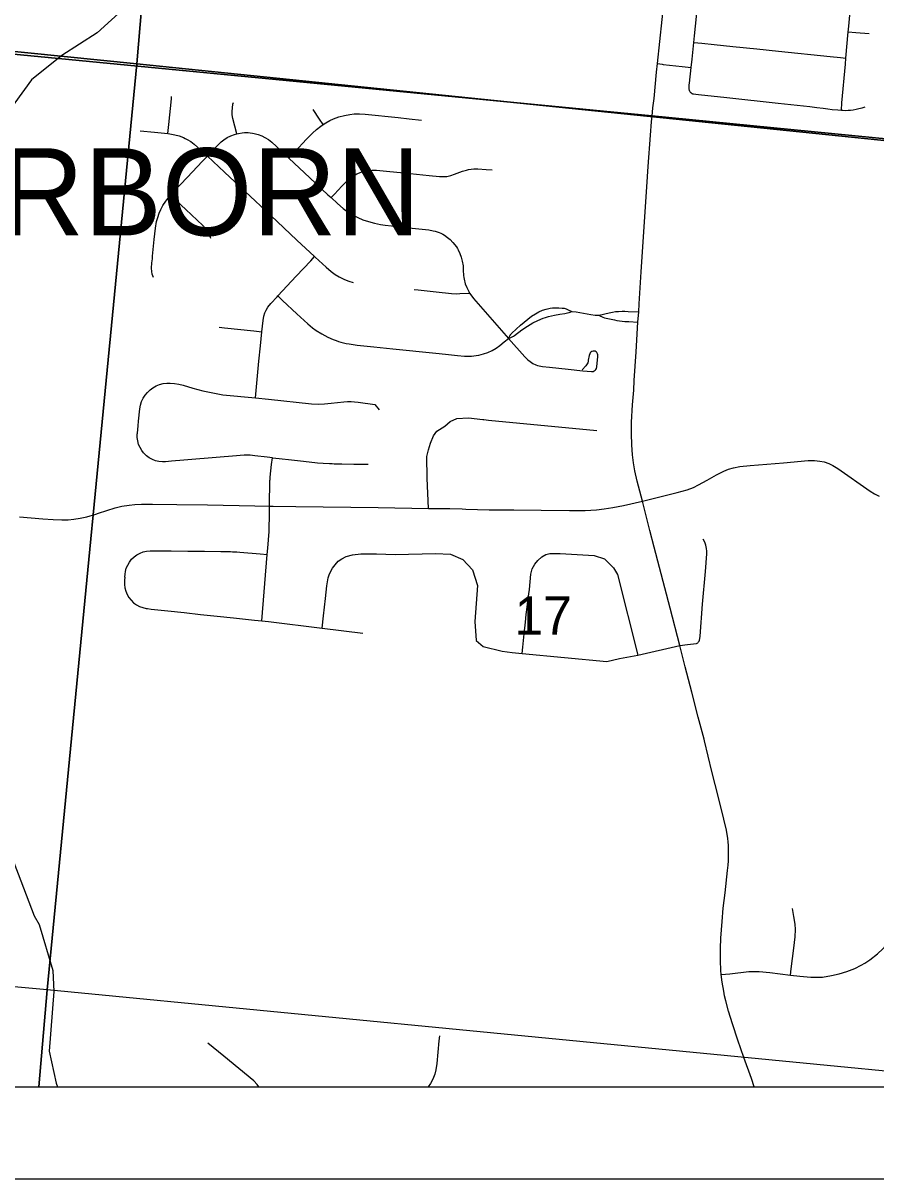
# Model space of a CAD drawing. Extents: x 0 to 34, y 0 to 22.
# Drawn here: x 26.733 to 27.66, y 13.362 to 14.618 of the extents above; entities that cross this region are included whole.
import ezdxf

# ---------------------------------------------------------------- set-up
doc = ezdxf.new("R2010")
doc.units = 0
for name, color, linetype in [('GM_X_City_Street', 7, 'Continuous'), ('GM_X_Corporation_Text', 7, 'Continuous'), ('GM_X_County_Road', 7, 'Continuous'), ('GM_X_Minor_River', 7, 'Continuous'), ('GM_X_Section', 7, 'Continuous'), ('GM_X_Section_Text', 7, 'Continuous'), ('GM_X_Township_Road', 7, 'Continuous'), ('SH_Border', 7, 'Continuous'), ('SH_Data', 7, 'Continuous')]:
    doc.layers.add(name, color=color, linetype=linetype)

msp = doc.modelspace()

# ---------------------------------------------------------------- linework, layer by layer
at = {"layer": 'GM_X_City_Street'}
for points in [[(27.6225, 14.5232), (27.6232, 14.5311), (27.6269, 14.5732), (27.6275, 14.5797), (27.63, 14.6083), (27.6303, 14.611), (27.632, 14.63), (27.6354, 14.6657), (27.6359, 14.6704), (27.6403, 14.7174), (27.6409, 14.7237), (27.6441, 14.7601), (27.6449, 14.77), (27.6454, 14.7759)], [(27.4592, 14.5419), (27.4586, 14.5424), (27.4581, 14.5431), (27.4578, 14.5437), (27.4575, 14.5443), (27.4573, 14.545), (27.4571, 14.5456), (27.457, 14.5463), (27.457, 14.5477), (27.4571, 14.5506), (27.4573, 14.5527), (27.4592, 14.5697), (27.4603, 14.5787), (27.4622, 14.5969), (27.463, 14.604), (27.4665, 14.6393)], [(27.63, 14.6083), (27.6381, 14.6076), (27.6528, 14.6065)], [(27.4622, 14.5969), (27.4707, 14.5961), (27.4843, 14.5947), (27.5047, 14.5925), (27.5307, 14.5898), (27.5542, 14.5873), (27.6105, 14.5814), (27.6217, 14.5803), (27.6275, 14.5797)], [(27.4226, 14.5738), (27.4278, 14.5731), (27.429, 14.573), (27.4495, 14.5707), (27.4592, 14.5697)], [(26.8905, 14.4977), (26.8914, 14.5075), (26.8943, 14.5354), (26.8946, 14.5379)], [(27.4592, 14.5419), (27.4603, 14.5413), (27.4609, 14.5411), (27.4617, 14.5409), (27.4642, 14.5405), (27.4673, 14.5402), (27.4982, 14.537), (27.5539, 14.531), (27.5883, 14.5272), (27.596, 14.5262), (27.6028, 14.5253), (27.6079, 14.5247), (27.6127, 14.5241), (27.6187, 14.5235), (27.6225, 14.5232), (27.6242, 14.5231), (27.6274, 14.523), (27.6299, 14.5231), (27.6324, 14.5232), (27.6352, 14.5235), (27.6385, 14.5242), (27.6414, 14.5249), (27.645, 14.5257), (27.6485, 14.5267)], [(26.9653, 14.4975), (26.9632, 14.5058), (26.9611, 14.5143), (26.9605, 14.5181), (26.9603, 14.52), (26.9603, 14.5219), (26.9606, 14.5258), (26.9612, 14.5296), (26.9617, 14.5314)], [(27.0592, 14.5076), (27.0553, 14.5134), (27.0483, 14.5241)], [(27.0219, 14.4712), (27.0284, 14.478), (27.0412, 14.4916), (27.0477, 14.4984), (27.0519, 14.5022), (27.0568, 14.506), (27.0592, 14.5076), (27.0621, 14.5095), (27.0665, 14.512), (27.0705, 14.5138), (27.0764, 14.5159), (27.0825, 14.5176), (27.0881, 14.5186), (27.0931, 14.5192), (27.0988, 14.5194), (27.105, 14.519), (27.1409, 14.5152), (27.1527, 14.5139), (27.1662, 14.5123)], [(26.8604, 14.5009), (26.8759, 14.4993), (26.8905, 14.4977), (26.8925, 14.4975), (26.898, 14.4966), (26.9027, 14.4953), (26.9073, 14.4936), (26.9093, 14.4926), (26.9116, 14.4915), (26.9153, 14.4892), (26.9192, 14.4863), (26.9261, 14.4802), (26.9334, 14.4734), (26.9519, 14.456), (26.9746, 14.4348), (27.0023, 14.4089), (27.0308, 14.3821), (27.05, 14.3641), (27.0507, 14.3634), (27.0626, 14.3525), (27.0679, 14.348), (27.0725, 14.3447), (27.0768, 14.3421), (27.0825, 14.3393), (27.0871, 14.3375), (27.092, 14.336)], [(26.8747, 14.3414), (26.8735, 14.345), (26.8729, 14.348), (26.8727, 14.3517), (26.8731, 14.3573), (26.8736, 14.3616), (26.8738, 14.3647), (26.8757, 14.3826), (26.8771, 14.395), (26.8783, 14.4023), (26.8794, 14.4066), (26.881, 14.4113), (26.8827, 14.4152), (26.8851, 14.4196), (26.8882, 14.4243), (26.8916, 14.4287), (26.8932, 14.4305), (26.8969, 14.4348), (26.9115, 14.4501), (26.9281, 14.4678), (26.9334, 14.4734), (26.9443, 14.4849), (26.9483, 14.4888), (26.9513, 14.4911), (26.955, 14.4934), (26.9589, 14.4953), (26.9629, 14.4969), (26.9653, 14.4975), (26.9671, 14.498), (26.9714, 14.4987), (26.9737, 14.4989), (26.9759, 14.4989), (26.9779, 14.4988), (26.9801, 14.4986), (26.9823, 14.4983), (26.9844, 14.4979), (26.9886, 14.4968), (26.9926, 14.4952), (26.996, 14.4936), (26.9997, 14.4913), (27.0036, 14.4883), (27.0087, 14.4836), (27.0219, 14.4712), (27.0449, 14.4497), (27.0644, 14.4313), (27.0678, 14.4282), (27.0749, 14.4217), (27.0811, 14.4165), (27.0866, 14.4124), (27.0918, 14.4091), (27.0968, 14.4065), (27.1025, 14.4041), (27.1084, 14.4021), (27.115, 14.4003), (27.1217, 14.399), (27.1268, 14.3983), (27.1337, 14.3974), (27.1455, 14.3962), (27.1595, 14.3948), (27.1741, 14.3931), (27.179, 14.3921), (27.1811, 14.3916), (27.1831, 14.3909), (27.1852, 14.3902), (27.1872, 14.3894), (27.1892, 14.3884), (27.191, 14.3874), (27.1946, 14.385), (27.1974, 14.3826), (27.2004, 14.3794), (27.2043, 14.3746), (27.2054, 14.3729), (27.2062, 14.3714), (27.208, 14.3674), (27.2094, 14.3633), (27.2105, 14.3591), (27.2113, 14.3542), (27.2115, 14.3493), (27.2118, 14.3437), (27.2121, 14.3413), (27.2125, 14.3394), (27.2138, 14.3346), (27.2153, 14.3305), (27.2175, 14.326), (27.2185, 14.3244), (27.2198, 14.3224), (27.2228, 14.3184), (27.2428, 14.2955), (27.2608, 14.2752), (27.2786, 14.255), (27.2816, 14.2519), (27.2841, 14.25), (27.2873, 14.248), (27.2906, 14.2465), (27.2924, 14.2458), (27.2942, 14.2453), (27.2978, 14.2446), (27.3053, 14.2438), (27.3256, 14.2416), (27.3417, 14.2401), (27.351, 14.2393), (27.3529, 14.2394), (27.354, 14.2398), (27.355, 14.2405), (27.3558, 14.2414), (27.3564, 14.2425), (27.3568, 14.2444), (27.3579, 14.2555), (27.3578, 14.2574), (27.3575, 14.2586), (27.3569, 14.2597), (27.356, 14.2605), (27.355, 14.2612), (27.3538, 14.2615), (27.3526, 14.2615), (27.3514, 14.2611), (27.3504, 14.2603), (27.3496, 14.2594), (27.349, 14.2583), (27.3484, 14.2566), (27.3475, 14.2516), (27.3472, 14.2498), (27.3468, 14.2487), (27.3463, 14.2475), (27.3456, 14.2464), (27.3449, 14.2454), (27.3408, 14.2411)], [(27.0678, 14.4282), (27.0715, 14.4321), (27.0795, 14.4408), (27.0853, 14.4465), (27.0891, 14.4498), (27.0922, 14.4519), (27.096, 14.4539), (27.1006, 14.4559), (27.1041, 14.457), (27.1084, 14.4578), (27.1127, 14.4582), (27.1171, 14.4582), (27.1283, 14.4571), (27.1468, 14.4551), (27.1746, 14.4521), (27.1858, 14.4511), (27.1907, 14.451), (27.1938, 14.4513), (27.1981, 14.4522), (27.2022, 14.4535), (27.2109, 14.4569), (27.215, 14.4582), (27.2174, 14.4588), (27.223, 14.4594), (27.2273, 14.4594), (27.2366, 14.4588), (27.2428, 14.4583)], [(26.9372, 14.3838), (26.9368, 14.385), (26.9351, 14.389), (26.9333, 14.3922), (26.9314, 14.3947), (26.9285, 14.3978), (26.91, 14.4153), (26.8995, 14.4249), (26.8932, 14.4305)], [(26.9892, 14.2503), (26.991, 14.267), (26.9927, 14.2825), (26.994, 14.2948), (26.9949, 14.2992), (26.996, 14.3029), (26.9973, 14.3058), (26.9993, 14.3091), (27.0025, 14.3131), (27.0092, 14.3205), (27.0099, 14.3213), (27.03, 14.3428), (27.0457, 14.3595), (27.05, 14.3641)], [(27.0099, 14.3213), (27.0152, 14.3164), (27.0306, 14.302), (27.0425, 14.291), (27.0477, 14.2866), (27.0518, 14.2837), (27.0577, 14.28), (27.0644, 14.2765), (27.0701, 14.274), (27.0734, 14.2728), (27.076, 14.2719), (27.0786, 14.2712), (27.0815, 14.2704), (27.0844, 14.2697), (27.0876, 14.2692), (27.0963, 14.268), (27.1142, 14.2662), (27.1351, 14.264), (27.1817, 14.259), (27.1924, 14.2579), (27.2054, 14.2566), (27.2128, 14.2559), (27.2179, 14.2558), (27.2204, 14.2559), (27.2229, 14.2562), (27.2257, 14.2565), (27.2285, 14.2571), (27.2334, 14.2583), (27.2382, 14.2599), (27.2428, 14.262), (27.2472, 14.2645), (27.2513, 14.2674), (27.2561, 14.2714), (27.2608, 14.2752)], [(27.1582, 14.3285), (27.1624, 14.328), (27.182, 14.3257), (27.1986, 14.3241), (27.2047, 14.3237), (27.2078, 14.3239), (27.2185, 14.3244)], [(27.2608, 14.2752), (27.2622, 14.2779), (27.2631, 14.2795), (27.2637, 14.2803), (27.2644, 14.281), (27.2738, 14.2894), (27.2858, 14.2992), (27.2899, 14.302), (27.2937, 14.3041), (27.2977, 14.3058), (27.3018, 14.3071), (27.3061, 14.308), (27.3084, 14.3083), (27.311, 14.3085), (27.3153, 14.3085), (27.3191, 14.3082), (27.3213, 14.3079), (27.3233, 14.3074), (27.3257, 14.3064), (27.3294, 14.3046)], [(27.2608, 14.2752), (27.2633, 14.2761), (27.2648, 14.2768), (27.2662, 14.2775), (27.2673, 14.2782), (27.2751, 14.2844), (27.2813, 14.2886), (27.2871, 14.2921), (27.2927, 14.2948), (27.2984, 14.2971), (27.301, 14.298), (27.3043, 14.299), (27.3109, 14.3006), (27.3164, 14.3016), (27.3219, 14.3023), (27.3235, 14.3025), (27.3248, 14.3028), (27.3268, 14.3034), (27.3294, 14.3046)], [(27.3294, 14.3046), (27.3342, 14.3039), (27.3501, 14.3011), (27.3548, 14.3006), (27.3594, 14.3003)], [(27.3594, 14.3003), (27.3701, 14.303), (27.3738, 14.3038), (27.3772, 14.3044), (27.3802, 14.3046), (27.3841, 14.3048), (27.3872, 14.3048), (27.3908, 14.3046), (27.4023, 14.304)], [(27.3594, 14.3003), (27.361, 14.2993), (27.3632, 14.2983), (27.3652, 14.2977), (27.3686, 14.2968), (27.376, 14.2952), (27.3785, 14.2947), (27.3815, 14.2943), (27.3842, 14.294), (27.387, 14.2937), (27.3914, 14.2935), (27.4014, 14.2928)], [(26.9464, 14.2875), (26.952, 14.2867), (26.9841, 14.2834), (26.9927, 14.2825)]]:
    msp.add_lwpolyline(points, dxfattribs=at)
at = {"layer": 'GM_X_County_Road'}
for p, q in [((27.4226, 14.5738), (27.4312, 14.6557)), ((27.4014, 14.2928), (27.4023, 14.304))]:
    msp.add_line(p, q, dxfattribs=at)
for points in [[(27.4168, 14.5166), (27.4177, 14.5256), (27.4189, 14.536), (27.4216, 14.5644), (27.4226, 14.5738)], [(27.4023, 14.304), (27.4029, 14.3129), (27.4049, 14.3476), (27.411, 14.4398), (27.4125, 14.4621), (27.4151, 14.4962), (27.4162, 14.5104), (27.4168, 14.5166)], [(27.3956, 14.2031), (27.3968, 14.219), (27.3973, 14.2296), (27.3995, 14.2607), (27.4014, 14.2928)], [(27.4062, 14.0982), (27.4004, 14.1202), (27.398, 14.1311), (27.3965, 14.1398), (27.3954, 14.1485), (27.3947, 14.1597), (27.3944, 14.1716), (27.3946, 14.1841), (27.3956, 14.2031)], [(26.8152, 14.0851), (26.8333, 14.091), (26.8405, 14.0927), (26.8484, 14.0941), (26.8545, 14.0947), (26.8619, 14.0951), (26.8737, 14.0951), (26.9004, 14.0946), (26.9334, 14.0942), (26.9849, 14.0932), (27.001, 14.0929)], [(27.001, 14.0929), (27.0048, 14.0928), (27.0297, 14.0926), (27.1192, 14.0913), (27.1739, 14.0904), (27.1969, 14.0902), (27.2102, 14.0898)], [(27.2102, 14.0898), (27.2142, 14.0897), (27.2397, 14.0889), (27.2664, 14.0888), (27.2962, 14.0885), (27.3269, 14.088), (27.344, 14.0882), (27.3565, 14.089), (27.3647, 14.0899), (27.374, 14.0913), (27.3857, 14.0935), (27.4062, 14.0982)], [(27.4469, 13.9416), (27.4365, 13.9822), (27.4191, 14.0483), (27.4144, 14.0663), (27.4062, 14.0982)], [(26.7293, 14.0812), (26.7547, 14.0791), (26.7659, 14.0783), (26.7752, 14.078), (26.7821, 14.0781), (26.7884, 14.0787), (26.7952, 14.0798), (26.8025, 14.0814), (26.8121, 14.0841), (26.8152, 14.0851)], [(27.4737, 13.8379), (27.4733, 13.8398), (27.467, 13.8637), (27.46, 13.8907), (27.4529, 13.9184), (27.4469, 13.9416)], [(27.492, 13.5838), (27.4916, 13.5883), (27.4914, 13.5917), (27.4913, 13.596), (27.4911, 13.6007), (27.4911, 13.6071), (27.4912, 13.6123), (27.4916, 13.6235), (27.4929, 13.6415), (27.4942, 13.656), (27.4961, 13.6726), (27.4989, 13.6971), (27.4994, 13.7027), (27.4997, 13.7076), (27.4999, 13.7125), (27.4999, 13.7168), (27.5, 13.7207), (27.4998, 13.7242), (27.4995, 13.7281), (27.4991, 13.7316), (27.4975, 13.7407), (27.4949, 13.7528), (27.4891, 13.7763), (27.4819, 13.8046), (27.4737, 13.8379)], [(27.5276, 13.4618), (27.5247, 13.4709), (27.5166, 13.4937), (27.5099, 13.5125), (27.5041, 13.5302), (27.5, 13.5439), (27.4969, 13.5553), (27.4956, 13.5609), (27.4947, 13.5657), (27.493, 13.5756), (27.492, 13.5838)]]:
    msp.add_lwpolyline(points, dxfattribs=at)
for points in [[(25.742, 13.4618), (26.7501, 13.4618), (26.7594, 13.5671), (25.7609, 13.6582)], [(26.7501, 13.4618), (27.7745, 13.4618), (27.7751, 13.4688), (26.7594, 13.5671)]]:
    msp.add_lwpolyline(points, close=True, dxfattribs=at)
at = {"layer": 'GM_X_Minor_River'}
for points in [[(26.8565, 14.6464), (26.8136, 14.6074), (26.7752, 14.5827), (26.7424, 14.5561), (26.7026, 14.5022)], [(26.7087, 13.7437), (26.7451, 13.6477), (26.7506, 13.6381), (26.7655, 13.5881), (26.7666, 13.5656), (26.7615, 13.5005), (26.7691, 13.4658), (26.7707, 13.4618)]]:
    msp.add_lwpolyline(points, dxfattribs=at)
at = {"layer": 'GM_X_Section'}
for points in [[(26.9382, 15.5362), (26.8568, 14.5735), (25.8618, 14.6744), (25.9494, 15.6396)], [(26.9382, 15.5362), (27.9506, 15.429), (27.8702, 14.4696), (26.8568, 14.5735)], [(26.8568, 14.5735), (26.7594, 13.5671), (25.7609, 13.6582), (25.8618, 14.6744)], [(26.8568, 14.5735), (27.8702, 14.4696), (27.7751, 13.4688), (26.7594, 13.5671)]]:
    msp.add_lwpolyline(points, close=True, dxfattribs=at)
at = {"layer": 'GM_X_Township_Road'}
for p, q in [((26.9856, 14.2106), (26.9892, 14.2503)), ((26.9925, 13.9682), (26.9985, 14.0404)), ((27.0581, 13.9603), (27.1024, 13.9549))]:
    msp.add_line(p, q, dxfattribs=at)
for points in [[(26.8587, 14.1854), (26.86, 14.1988), (26.8608, 14.2027), (26.862, 14.2065), (26.8637, 14.2101), (26.8658, 14.2134), (26.8683, 14.2165), (26.8711, 14.2192), (26.8743, 14.2216), (26.8778, 14.2235), (26.8814, 14.225), (26.8852, 14.2261), (26.8892, 14.2267), (26.8931, 14.2267), (26.8978, 14.2262), (26.9025, 14.2254), (26.9071, 14.2243), (26.9177, 14.2211), (26.9284, 14.2183), (26.9392, 14.2159), (26.9501, 14.214), (26.9856, 14.2106)], [(26.9856, 14.2106), (26.9998, 14.209), (27.0467, 14.204), (27.0538, 14.2039), (27.0609, 14.2042), (27.068, 14.2048), (27.0819, 14.2062), (27.0857, 14.2066), (27.0896, 14.2066), (27.0935, 14.2064), (27.0974, 14.2059), (27.1155, 14.2032), (27.1203, 14.1977)], [(27.0041, 14.1455), (26.9983, 14.1461), (26.9851, 14.1476), (26.9799, 14.1482), (26.9758, 14.1483), (26.9744, 14.1482), (26.9734, 14.1482), (26.9607, 14.1471), (26.9475, 14.146), (26.9342, 14.1449), (26.921, 14.1438), (26.9078, 14.1427), (26.8946, 14.1416), (26.8879, 14.141), (26.8846, 14.1409), (26.8808, 14.1413), (26.8772, 14.1422), (26.8736, 14.1436), (26.8703, 14.1454), (26.8672, 14.1476), (26.8645, 14.1503), (26.8639, 14.151), (26.8621, 14.1532), (26.8602, 14.1565), (26.8587, 14.16), (26.8577, 14.1637), (26.8572, 14.1674), (26.8572, 14.1712), (26.8573, 14.1722), (26.8581, 14.18), (26.8587, 14.1854)], [(27.1739, 14.0904), (27.1725, 14.1232), (27.1718, 14.1468), (27.1738, 14.1541), (27.1758, 14.1613), (27.1791, 14.1692), (27.183, 14.1745), (27.1916, 14.1797), (27.1975, 14.185), (27.2047, 14.1883), (27.2172, 14.1889), (27.233, 14.187)], [(27.233, 14.187), (27.234, 14.1869), (27.2389, 14.1863), (27.3568, 14.175)], [(27.001, 14.0929), (27.0011, 14.105), (27.0012, 14.1097), (27.0014, 14.1192), (27.0014, 14.1207), (27.0015, 14.1219), (27.0018, 14.1245), (27.0033, 14.138), (27.0041, 14.1455)], [(27.0041, 14.1455), (27.0115, 14.1447), (27.0247, 14.1433), (27.0379, 14.1418), (27.0532, 14.1401), (27.0593, 14.1396), (27.0661, 14.1392), (27.069, 14.1391), (27.0711, 14.139), (27.0794, 14.1389), (27.0927, 14.1387), (27.1081, 14.1385)], [(27.4062, 14.0982), (27.4442, 14.1079), (27.455, 14.1108), (27.4619, 14.1132), (27.4674, 14.1159), (27.4765, 14.1211), (27.4867, 14.1271), (27.4946, 14.131), (27.4998, 14.1331), (27.5053, 14.1347), (27.5121, 14.1359), (27.5233, 14.137), (27.5598, 14.1401), (27.5865, 14.1424), (27.5934, 14.1425), (27.5991, 14.1419), (27.604, 14.1409), (27.6088, 14.1392), (27.6134, 14.137), (27.6188, 14.1337), (27.6539, 14.1092), (27.6587, 14.1063), (27.6636, 14.1039)], [(26.9985, 14.0404), (26.999, 14.0473), (27.0005, 14.0652), (27.0007, 14.0686), (27.0008, 14.0827), (27.001, 14.0929)], [(27.4469, 13.9416), (27.4554, 13.9426), (27.465, 13.9437), (27.4658, 13.9439), (27.4664, 13.9443), (27.467, 13.9449), (27.4674, 13.9454), (27.4679, 13.9463), (27.4683, 13.9474), (27.4686, 13.949), (27.4689, 13.9516), (27.4717, 13.9863), (27.4747, 14.0217), (27.4763, 14.0409), (27.4764, 14.0438), (27.4761, 14.0467), (27.4757, 14.0488), (27.4752, 14.0506), (27.4746, 14.0525), (27.4737, 14.0545), (27.4723, 14.057)], [(26.8436, 14.0156), (26.8439, 14.0188), (26.8443, 14.0217), (26.8453, 14.0254), (26.8468, 14.0289), (26.8487, 14.0322), (26.8511, 14.0351), (26.8538, 14.0378), (26.8569, 14.04), (26.8602, 14.0419), (26.8637, 14.0432), (26.8674, 14.0441), (26.8712, 14.0445), (26.8725, 14.0445), (26.8762, 14.0444), (26.8942, 14.0442), (26.9122, 14.044), (26.9302, 14.0438), (26.9482, 14.0436), (26.9586, 14.0435), (26.9609, 14.0434), (26.9653, 14.0431), (26.9687, 14.0429), (26.9909, 14.041), (26.9985, 14.0404)], [(27.0581, 13.9603), (27.0595, 13.9737), (27.0618, 13.9927), (27.0632, 14.0063), (27.0647, 14.0149), (27.066, 14.0193), (27.0695, 14.0254), (27.0722, 14.0293), (27.0756, 14.033), (27.0794, 14.0357), (27.0842, 14.0381), (27.091, 14.0401), (27.1002, 14.0411), (27.1173, 14.0409), (27.1374, 14.0405), (27.1814, 14.0416), (27.1977, 14.0406), (27.2111, 14.0349), (27.2217, 14.0238), (27.2272, 14.0067), (27.224, 13.9676), (27.2255, 13.947), (27.2331, 13.9404), (27.2537, 13.9352), (27.2648, 13.9339), (27.2755, 13.9329), (27.3675, 13.9241), (27.3813, 13.9272), (27.4013, 13.9309), (27.4469, 13.9416)], [(27.2755, 13.9329), (27.2762, 13.9396), (27.2779, 13.9541), (27.2792, 13.9667), (27.2801, 13.9753), (27.2809, 13.9832), (27.2821, 13.9928), (27.2834, 14.0024), (27.2851, 14.019), (27.2866, 14.0249), (27.2893, 14.0298), (27.2925, 14.0338), (27.2969, 14.0377), (27.3014, 14.0402), (27.3055, 14.0414), (27.3168, 14.0416), (27.3537, 14.0392), (27.3651, 14.0357), (27.3747, 14.026), (27.3791, 14.0186), (27.4013, 13.9309)], [(26.8436, 14.0156), (26.8433, 14.0125), (26.8432, 14.0116), (26.8432, 14.0078), (26.8437, 14.0041), (26.8447, 14.0004), (26.8462, 13.9969), (26.8481, 13.9937), (26.8505, 13.9907), (26.8532, 13.988), (26.8563, 13.9858), (26.8596, 13.984), (26.8631, 13.9826), (26.8668, 13.9817), (26.8685, 13.9815), (26.8724, 13.9811), (26.8903, 13.9792), (26.9082, 13.9772), (26.9261, 13.9753), (26.944, 13.9734), (26.9619, 13.9715), (26.9847, 13.969), (26.9925, 13.9682)], [(26.9925, 13.9682), (26.9998, 13.9674), (27.0581, 13.9603)], [(27.5671, 13.5833), (27.5775, 13.582), (27.5892, 13.5811), (27.5966, 13.581), (27.6021, 13.5812), (27.6118, 13.5827), (27.6202, 13.5846), (27.6284, 13.5871), (27.6371, 13.5905), (27.6442, 13.594), (27.6479, 13.5962), (27.6534, 13.6), (27.6617, 13.6064), (27.6676, 13.6118), (27.6729, 13.6178), (27.6786, 13.6251), (27.6829, 13.6318), (27.6876, 13.6405), (27.6935, 13.6534), (27.6996, 13.6683), (27.7082, 13.689), (27.7188, 13.7135), (27.7195, 13.7151)], [(27.5671, 13.5833), (27.5679, 13.5902), (27.5708, 13.6124), (27.5722, 13.6248), (27.5726, 13.6329), (27.5723, 13.6385), (27.5709, 13.6471), (27.5693, 13.6557)], [(27.492, 13.5838), (27.5014, 13.5848), (27.5218, 13.587), (27.5287, 13.5873), (27.5331, 13.5873), (27.5449, 13.5862), (27.5671, 13.5833)], [(27.1856, 13.5172), (27.1851, 13.5119), (27.1829, 13.4871), (27.1819, 13.4803), (27.1806, 13.4755), (27.1786, 13.4703), (27.176, 13.4654), (27.1734, 13.4618)], [(26.9895, 13.4618), (26.9877, 13.4642), (26.9838, 13.4682), (26.9512, 13.495), (26.9339, 13.5093)]]:
    msp.add_lwpolyline(points, dxfattribs=at)
at = {"layer": 'SH_Border'}
for points in [[(28.3712, 14.4228), (27.8734, 14.472), (27.4166, 14.5171), (26.5575, 14.5999), (26.3631, 14.6275), (25.9925, 14.6654), (25.9218, 14.6726), (25.8798, 14.6769), (25.8593, 14.6788), (25.2424, 14.7363)], [(25.2424, 14.7363), (25.8593, 14.6788), (25.8798, 14.6769), (25.9218, 14.6726), (25.9925, 14.6654), (26.3631, 14.6275), (26.5575, 14.5999), (27.4166, 14.5171), (27.8734, 14.472), (28.3712, 14.4228)], [(22.5164, 13.4618), (28.7843, 13.4618)]]:
    msp.add_lwpolyline(points, dxfattribs=at)
at = {"layer": 'SH_Data'}
for p, q in [((22.5164, 13.4618), (29.3164, 13.4618)), ((22.4164, 13.3618), (29.4164, 13.3618))]:
    msp.add_line(p, q, dxfattribs=at)
msp.add_lwpolyline([(22.5164, 19.0318), (22.5164, 13.4618), (29.3164, 13.4618)], dxfattribs=at)

# ---------------------------------------------------------------- texts
at = {"layer": 'GM_X_Corporation_Text'}
msp.add_text('FAIRBORN', height=0.0947, rotation=0, dxfattribs=at).set_placement((26.5109, 14.3871))
at = {"layer": 'GM_X_Section_Text'}
msp.add_text('17', height=0.04186, rotation=0, dxfattribs=at).set_placement((27.2673, 13.9532))

doc.saveas('drawing.dxf')
